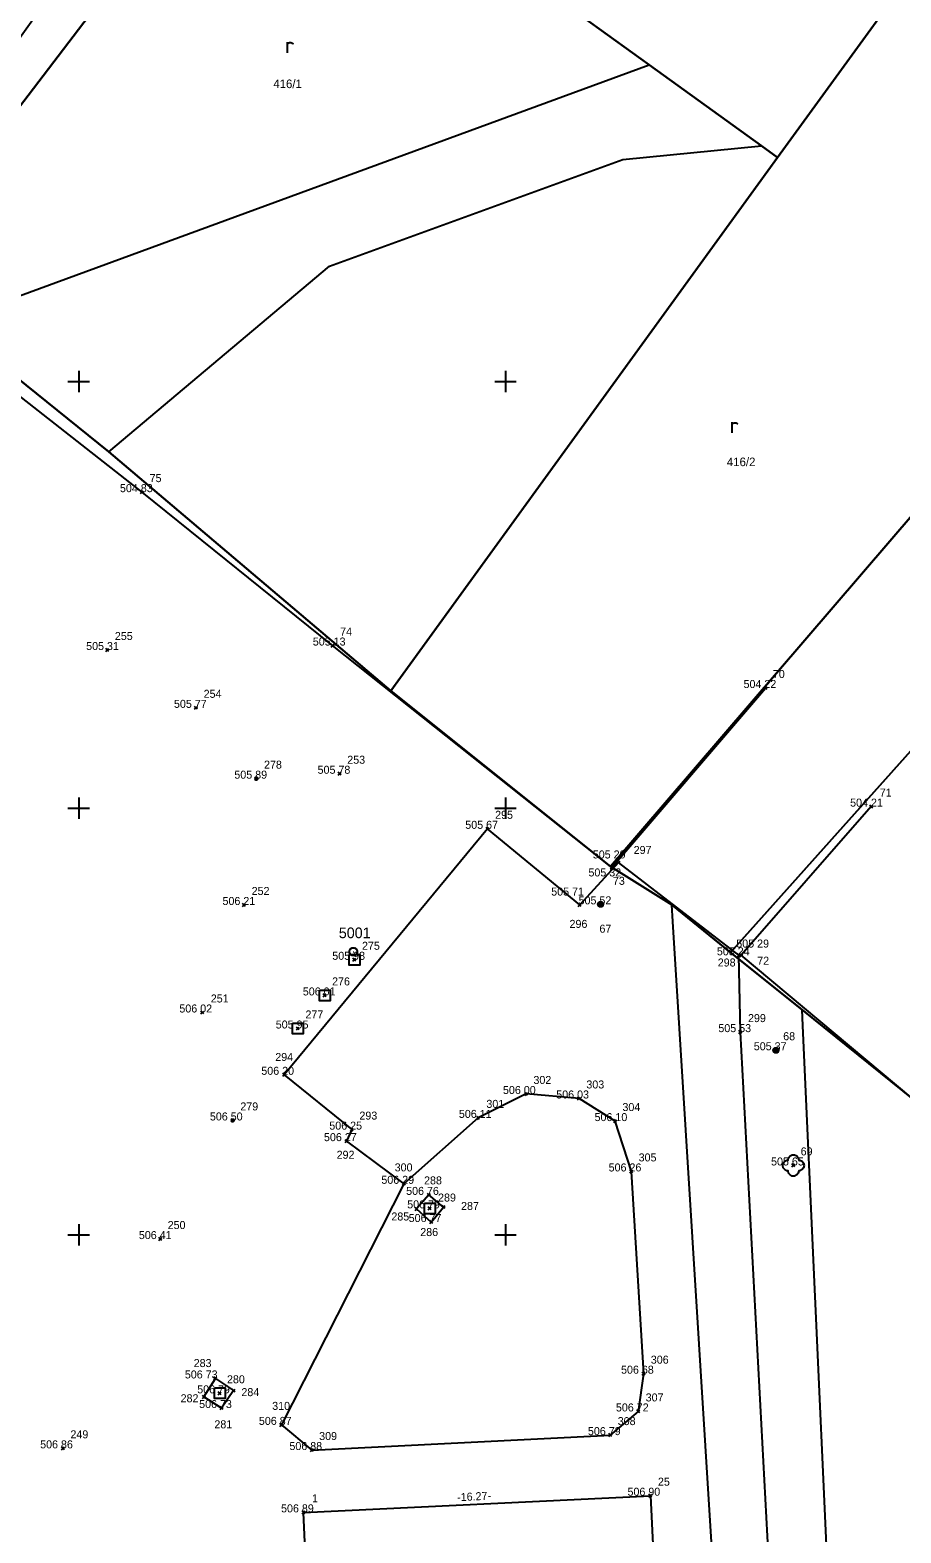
# Model space of a CAD drawing. Extents: x -408550 to -407654, y -1233019 to -1231230.
# Drawn here: x -408002.3 to -407961.5, y -1232014 to -1231943.5 of the extents above; entities that cross this region are included whole.
import ezdxf

# ---------------------------------------------------------------- set-up
doc = ezdxf.new("R2010")
doc.units = 0
for name, color, linetype in [('Level 1', 7, 'Continuous'), ('Level 11', 7, 'Continuous'), ('Level 12', 7, 'Continuous'), ('Level 14', 7, 'Continuous'), ('Level 16', 7, 'Continuous'), ('Level 20', 7, 'Continuous'), ('Level 23', 7, 'Continuous'), ('Level 26', 7, 'Continuous'), ('Level 28', 7, 'Continuous'), ('Level 30', 7, 'Continuous'), ('Level 40', 7, 'Continuous'), ('Level 41', 7, 'Continuous'), ('Level 45', 7, 'Continuous'), ('Level 47', 7, 'Continuous'), ('Level 5', 7, 'Continuous')]:
    doc.layers.add(name, color=color, linetype=linetype)

msp = doc.modelspace()

# ---------------------------------------------------------------- linework, layer by layer
at = {"layer": 'Level 1'}
for p, q in [((-408000, -1231959.5), (-408000, -1231960.5)), ((-407980, -1231959.5), (-407980, -1231960.5)), ((-408000.5, -1231960), (-407999.5, -1231960)), ((-407980.5, -1231960), (-407979.5, -1231960)), ((-408000, -1231979.5), (-408000, -1231980.5)), ((-407980, -1231979.5), (-407980, -1231980.5)), ((-408000.5, -1231980), (-407999.5, -1231980)), ((-407980.5, -1231980), (-407979.5, -1231980)), ((-408000, -1231999.5), (-408000, -1232000.5)), ((-407980, -1231999.5), (-407980, -1232000.5)), ((-408000.5, -1232000), (-407999.5, -1232000)), ((-407980.5, -1232000), (-407979.5, -1232000))]:
    msp.add_line(p, q, dxfattribs=at)
for points in [[(-407991.04, -1231886.54), (-407990.51, -1231886.91), (-407979.53, -1231894.66), (-407981.86, -1231897.95), (-407972.2, -1231905.71), (-407991.32, -1231932.1), (-408007.06, -1231952.72), (-408008.8, -1231955), (-408010, -1231954.02), (-407982.21, -1231915.1), (-407987.32, -1231909.48), (-407982.96, -1231899.31), (-407994.22, -1231890.85)], [(-407936.88, -1231940.71), (-407927.62, -1231929.33), (-407925.46, -1231926.55), (-407918.2, -1231917), (-407912.81, -1231921.49), (-407927.97, -1231939.1), (-407932.78, -1231945.57), (-407935.18, -1231948.41), (-407939.36, -1231953.09), (-407969.45, -1231986.76), (-407972.21, -1231984.54), (-407975.08, -1231982.73), (-407945.1, -1231947.81), (-407942.31, -1231945.07)], [(-407991.32, -1231932.1), (-407979.12, -1231940.92), (-407973.26, -1231945.16), (-407968, -1231948.96), (-407967.25, -1231949.5), (-407985.37, -1231974.5), (-407998.58, -1231963.3), (-408002.95, -1231959.78), (-408005.56, -1231957.64), (-408008.8, -1231955), (-408007.06, -1231952.72)], [(-407945.1, -1231947.81), (-407975.08, -1231982.73), (-407985.37, -1231974.5), (-407967.25, -1231949.5), (-407961.01, -1231940.9)], [(-407927.1, -1231965.2), (-407931.57, -1231970.36), (-407955.64, -1231997.88), (-407966.11, -1231989.44), (-407969.45, -1231986.76), (-407939.36, -1231953.09)]]:
    msp.add_lwpolyline(points, close=True, dxfattribs=at)
for points in [[(-407945.83, -1231920.05), (-407949.91, -1231925.78), (-407952.31, -1231929.14), (-407961.01, -1231940.9), (-407967.25, -1231949.5), (-407968, -1231948.96), (-407973.26, -1231945.16), (-407979.12, -1231940.92), (-407957.82, -1231911.87), (-407949.85, -1231917.72)], [(-407990.21, -1231944.59), (-407990.21, -1231944.09)], [(-407990.21, -1231944.19), (-407990.185, -1231944.157), (-407990.152, -1231944.13), (-407990.117, -1231944.117), (-407990.06, -1231944.115), (-407990.017, -1231944.122), (-407989.992, -1231944.14), (-407989.97, -1231944.165), (-407989.96, -1231944.19)], [(-408002.95, -1231959.78), (-407998.58, -1231963.3), (-407985.37, -1231974.5), (-407975.08, -1231982.73), (-407972.21, -1231984.54), (-407969.45, -1231986.76), (-407966.11, -1231989.44), (-407955.64, -1231997.88), (-407939.09, -1232011.47), (-407927.08, -1232021.88), (-407908.02, -1232037.31)], [(-407969.38, -1231962.41), (-407969.38, -1231961.91)], [(-407969.38, -1231962.01), (-407969.355, -1231961.978), (-407969.323, -1231961.95), (-407969.288, -1231961.938), (-407969.23, -1231961.935), (-407969.188, -1231961.943), (-407969.163, -1231961.96), (-407969.14, -1231961.985), (-407969.13, -1231962.01)]]:
    msp.add_lwpolyline(points, dxfattribs=at)
at = {"layer": 'Level 11'}
msp.add_lwpolyline([(-407989.46, -1232013.01), (-407973.21, -1232012.23), (-407971.98, -1232037.5), (-407977.95, -1232037.78), (-407977.733, -1232042.415), (-407976.39, -1232042.37), (-407976.14, -1232046.74), (-407977.45, -1232046.87), (-407977.009, -1232051.318), (-407974.962, -1232053.765), (-407970.82, -1232049.62), (-407949.71, -1232072.37), (-407961.89, -1232083.71), (-407983.01, -1232060.92), (-407980.3, -1232058.38), (-407984.06, -1232054.32), (-407985.01, -1232038.14), (-407988.32, -1232038.28)], close=True, dxfattribs=at)
at = {"layer": 'Level 12'}
for p, q in [((-407975.01, -1231982.78), (-407967.81, -1231974.37)), ((-407962.86, -1231979.93), (-407968.95, -1231986.9))]:
    msp.add_line(p, q, dxfattribs=at)
msp.add_lwpolyline([(-407921.23, -1232026.55), (-407939.09, -1232011.64), (-407955.83, -1231997.88), (-407968.95, -1231986.9), (-407969.06, -1231986.9), (-407974.7, -1231982.55), (-407975.01, -1231982.78), (-407988.1, -1231972.38), (-407997.03, -1231965.19), (-408008.57, -1231956.14), (-408021.93, -1231961.96), (-408037.34, -1231968.54), (-408046.88, -1231972.68)], dxfattribs=at)
at = {"layer": 'Level 14'}
msp.add_lwpolyline([(-407974.7, -1231982.55), (-407976.52, -1231984.54), (-407980.84, -1231980.97), (-407990.37, -1231992.5), (-407987.2, -1231995.07), (-407987.45, -1231995.61), (-407984.76, -1231997.61)], dxfattribs=at)
msp.add_lwpolyline([(-407984.76, -1231997.61), (-407990.5, -1232008.91), (-407989.07, -1232010.09), (-407975.08, -1232009.39), (-407973.77, -1232008.28), (-407973.52, -1232006.51), (-407974.1, -1231997.03), (-407974.86, -1231994.67), (-407976.55, -1231993.61), (-407979.03, -1231993.4), (-407981.28, -1231994.52)], close=True, dxfattribs=at)
at = {"layer": 'Level 16'}
msp.add_lwpolyline([(-407975.55, -1232046.38), (-407966.48, -1232045.77), (-407966.78, -1232037.84), (-407966.87, -1232034.48), (-407966.71, -1232034.46), (-407967.34, -1232021.13), (-407968.99, -1231990.5), (-407969.06, -1231986.9)], dxfattribs=at)
for points in [[(-407983.59, -1231998.13), (-407984.17, -1231998.79), (-407983.48, -1231999.4), (-407982.9, -1231998.7)], [(-407994.13, -1232007.6), (-407993.59, -1232006.73), (-407992.74, -1232007.3), (-407993.3, -1232008.12)]]:
    msp.add_lwpolyline(points, close=True, dxfattribs=at)
at = {"layer": 'Level 20'}
for points in [[(-407987.33, -1231986.86), (-407986.83, -1231986.86), (-407986.83, -1231987.36), (-407987.33, -1231987.36)], [(-407988.72, -1231988.53), (-407988.22, -1231988.53), (-407988.22, -1231989.03), (-407988.72, -1231989.03)], [(-407989.98, -1231990.08), (-407989.48, -1231990.08), (-407989.48, -1231990.58), (-407989.98, -1231990.58)], [(-407983.8, -1231998.51), (-407983.3, -1231998.51), (-407983.3, -1231999.01), (-407983.8, -1231999.01)], [(-407993.64, -1232007.18), (-407993.14, -1232007.18), (-407993.14, -1232007.68), (-407993.64, -1232007.68)]]:
    msp.add_lwpolyline(points, close=True, dxfattribs=at)
at = {"layer": 'Level 23'}
for points in [[(-407996.961, -1231965.259), (-407997.099, -1231965.121)], [(-407997.099, -1231965.259), (-407996.961, -1231965.121)], [(-407998.591, -1231972.659), (-407998.729, -1231972.521)], [(-407998.729, -1231972.659), (-407998.591, -1231972.521)], [(-407988.031, -1231972.449), (-407988.169, -1231972.311)], [(-407988.169, -1231972.449), (-407988.031, -1231972.311)], [(-407967.741, -1231974.439), (-407967.879, -1231974.301)], [(-407967.879, -1231974.439), (-407967.741, -1231974.301)], [(-407994.431, -1231975.369), (-407994.569, -1231975.231)], [(-407994.569, -1231975.369), (-407994.431, -1231975.231)], [(-407991.601, -1231978.689), (-407991.739, -1231978.551)], [(-407991.739, -1231978.689), (-407991.601, -1231978.551)], [(-407987.701, -1231978.459), (-407987.839, -1231978.321)], [(-407987.839, -1231978.459), (-407987.701, -1231978.321)], [(-407962.791, -1231979.999), (-407962.929, -1231979.861)], [(-407962.929, -1231979.999), (-407962.791, -1231979.861)], [(-407980.771, -1231981.039), (-407980.909, -1231980.901)], [(-407980.909, -1231981.039), (-407980.771, -1231980.901)], [(-407974.941, -1231982.849), (-407975.079, -1231982.711)], [(-407975.079, -1231982.849), (-407974.941, -1231982.711)], [(-407974.631, -1231982.619), (-407974.769, -1231982.481)], [(-407974.769, -1231982.619), (-407974.631, -1231982.481)], [(-407992.181, -1231984.609), (-407992.319, -1231984.471)], [(-407992.319, -1231984.609), (-407992.181, -1231984.471)], [(-407976.451, -1231984.609), (-407976.589, -1231984.471)], [(-407976.589, -1231984.609), (-407976.451, -1231984.471)], [(-407975.471, -1231984.579), (-407975.609, -1231984.441)], [(-407975.609, -1231984.579), (-407975.471, -1231984.441)], [(-407968.991, -1231986.969), (-407969.129, -1231986.831)], [(-407969.129, -1231986.969), (-407968.991, -1231986.831)], [(-407968.881, -1231986.969), (-407969.019, -1231986.831)], [(-407969.019, -1231986.969), (-407968.881, -1231986.831)], [(-407987.011, -1231987.179), (-407987.149, -1231987.041)], [(-407987.149, -1231987.179), (-407987.011, -1231987.041)], [(-407988.401, -1231988.849), (-407988.539, -1231988.711)], [(-407988.539, -1231988.849), (-407988.401, -1231988.711)], [(-407994.141, -1231989.649), (-407994.279, -1231989.511)], [(-407994.279, -1231989.649), (-407994.141, -1231989.511)], [(-407989.661, -1231990.399), (-407989.799, -1231990.261)], [(-407989.799, -1231990.399), (-407989.661, -1231990.261)], [(-407968.921, -1231990.569), (-407969.059, -1231990.431)], [(-407969.059, -1231990.569), (-407968.921, -1231990.431)], [(-407967.261, -1231991.419), (-407967.399, -1231991.281)], [(-407967.399, -1231991.419), (-407967.261, -1231991.281)], [(-407990.301, -1231992.569), (-407990.439, -1231992.431)], [(-407990.439, -1231992.569), (-407990.301, -1231992.431)], [(-407978.961, -1231993.469), (-407979.099, -1231993.331)], [(-407979.099, -1231993.469), (-407978.961, -1231993.331)], [(-407976.481, -1231993.679), (-407976.619, -1231993.541)], [(-407976.619, -1231993.679), (-407976.481, -1231993.541)], [(-407992.711, -1231994.709), (-407992.849, -1231994.571)], [(-407992.849, -1231994.709), (-407992.711, -1231994.571)], [(-407981.211, -1231994.589), (-407981.349, -1231994.451)], [(-407981.349, -1231994.589), (-407981.211, -1231994.451)], [(-407974.791, -1231994.739), (-407974.929, -1231994.601)], [(-407974.929, -1231994.739), (-407974.791, -1231994.601)], [(-407987.131, -1231995.139), (-407987.269, -1231995.001)], [(-407987.269, -1231995.139), (-407987.131, -1231995.001)], [(-407987.381, -1231995.679), (-407987.519, -1231995.541)], [(-407987.519, -1231995.679), (-407987.381, -1231995.541)], [(-407966.441, -1231996.819), (-407966.579, -1231996.681)], [(-407966.579, -1231996.819), (-407966.441, -1231996.681)], [(-407984.691, -1231997.679), (-407984.829, -1231997.541)], [(-407984.829, -1231997.679), (-407984.691, -1231997.541)], [(-407974.031, -1231997.099), (-407974.169, -1231996.961)], [(-407974.169, -1231997.099), (-407974.031, -1231996.961)], [(-407983.521, -1231998.199), (-407983.659, -1231998.061)], [(-407983.659, -1231998.199), (-407983.521, -1231998.061)], [(-407984.101, -1231998.859), (-407984.239, -1231998.721)], [(-407984.239, -1231998.859), (-407984.101, -1231998.721)], [(-407983.481, -1231998.829), (-407983.619, -1231998.691)], [(-407983.619, -1231998.829), (-407983.481, -1231998.691)], [(-407982.831, -1231998.769), (-407982.969, -1231998.631)], [(-407982.969, -1231998.769), (-407982.831, -1231998.631)], [(-407983.411, -1231999.469), (-407983.549, -1231999.331)], [(-407983.549, -1231999.469), (-407983.411, -1231999.331)], [(-407996.101, -1232000.269), (-407996.239, -1232000.131)], [(-407996.239, -1232000.269), (-407996.101, -1232000.131)], [(-407993.521, -1232006.799), (-407993.659, -1232006.661)], [(-407993.659, -1232006.799), (-407993.521, -1232006.661)], [(-407973.451, -1232006.579), (-407973.589, -1232006.441)], [(-407973.589, -1232006.579), (-407973.451, -1232006.441)], [(-407993.321, -1232007.499), (-407993.459, -1232007.361)], [(-407993.459, -1232007.499), (-407993.321, -1232007.361)], [(-407992.671, -1232007.369), (-407992.809, -1232007.231)], [(-407992.809, -1232007.369), (-407992.671, -1232007.231)], [(-407994.061, -1232007.669), (-407994.199, -1232007.531)], [(-407994.199, -1232007.669), (-407994.061, -1232007.531)], [(-407993.231, -1232008.189), (-407993.369, -1232008.051)], [(-407993.369, -1232008.189), (-407993.231, -1232008.051)], [(-407990.431, -1232008.979), (-407990.569, -1232008.841)], [(-407990.569, -1232008.979), (-407990.431, -1232008.841)], [(-407973.701, -1232008.349), (-407973.839, -1232008.211)], [(-407973.839, -1232008.349), (-407973.701, -1232008.211)], [(-407975.011, -1232009.459), (-407975.149, -1232009.321)], [(-407975.149, -1232009.459), (-407975.011, -1232009.321)], [(-408000.671, -1232010.079), (-408000.809, -1232009.941)], [(-408000.809, -1232010.079), (-408000.671, -1232009.941)], [(-407989.001, -1232010.159), (-407989.139, -1232010.021)], [(-407989.139, -1232010.159), (-407989.001, -1232010.021)], [(-407973.141, -1232012.299), (-407973.279, -1232012.161)], [(-407973.279, -1232012.299), (-407973.141, -1232012.161)], [(-407989.391, -1232013.079), (-407989.529, -1232012.941)], [(-407989.529, -1232013.079), (-407989.391, -1232012.941)]]:
    msp.add_lwpolyline(points, dxfattribs=at)
at = {"layer": 'Level 28'}
msp.add_lwpolyline([(-407966.01, -1231996.75), (-407966.035, -1231996.858), (-407966.104, -1231996.946), (-407966.204, -1231996.994), (-407966.26, -1231997), (-407966.285, -1231997.108), (-407966.354, -1231997.196), (-407966.454, -1231997.244), (-407966.566, -1231997.244), (-407966.666, -1231997.196), (-407966.735, -1231997.108), (-407966.76, -1231997), (-407966.816, -1231996.994), (-407966.916, -1231996.946), (-407966.985, -1231996.858), (-407967.01, -1231996.75), (-407966.985, -1231996.642), (-407966.916, -1231996.554), (-407966.816, -1231996.506), (-407966.76, -1231996.5), (-407966.735, -1231996.392), (-407966.666, -1231996.304), (-407966.566, -1231996.256), (-407966.454, -1231996.256), (-407966.354, -1231996.304), (-407966.285, -1231996.392), (-407966.26, -1231996.5), (-407966.204, -1231996.506), (-407966.104, -1231996.554), (-407966.035, -1231996.642)], close=True, dxfattribs=at)
msp.add_lwpolyline([(-407966.522, -1231996.75), (-407966.51, -1231996.75), (-407966.498, -1231996.75)], dxfattribs=at)
at = {"layer": 'Level 30'}
msp.add_lwpolyline([(-407987.082, -1231986.549), (-407986.998, -1231986.598), (-407986.949, -1231986.682), (-407986.949, -1231986.778), (-407986.998, -1231986.862), (-407987.082, -1231986.911), (-407987.178, -1231986.911), (-407987.262, -1231986.862), (-407987.311, -1231986.778), (-407987.311, -1231986.682), (-407987.262, -1231986.598), (-407987.178, -1231986.549)], close=True, dxfattribs=at)
msp.add_lwpolyline([(-407987.142, -1231986.73), (-407987.118, -1231986.73)], dxfattribs=at)
at = {"layer": 'Level 45'}
for points in [[(-407975.579, -1231984.391), (-407975.501, -1231984.391), (-407975.439, -1231984.436), (-407975.415, -1231984.51), (-407975.439, -1231984.584), (-407975.501, -1231984.629), (-407975.579, -1231984.629), (-407975.641, -1231984.584), (-407975.665, -1231984.51), (-407975.641, -1231984.436), (-407975.579, -1231984.391), (-407975.57, -1231984.4), (-407975.51, -1231984.4), (-407975.47, -1231984.42), (-407975.61, -1231984.42), (-407975.63, -1231984.44), (-407975.45, -1231984.44), (-407975.45, -1231984.46), (-407975.63, -1231984.46), (-407975.64, -1231984.48), (-407975.44, -1231984.48), (-407975.43, -1231984.5), (-407975.65, -1231984.5), (-407975.65, -1231984.52), (-407975.43, -1231984.52), (-407975.438, -1231984.54), (-407975.641, -1231984.54), (-407975.64, -1231984.56), (-407975.438, -1231984.56), (-407975.45, -1231984.58), (-407975.63, -1231984.58), (-407975.61, -1231984.6), (-407975.47, -1231984.6), (-407975.497, -1231984.62), (-407975.582, -1231984.62)], [(-407967.369, -1231991.231), (-407967.291, -1231991.231), (-407967.229, -1231991.277), (-407967.205, -1231991.35), (-407967.229, -1231991.424), (-407967.291, -1231991.469), (-407967.369, -1231991.469), (-407967.431, -1231991.424), (-407967.455, -1231991.35), (-407967.431, -1231991.277), (-407967.369, -1231991.231), (-407967.36, -1231991.24), (-407967.3, -1231991.24), (-407967.26, -1231991.26), (-407967.4, -1231991.26), (-407967.42, -1231991.28), (-407967.24, -1231991.28), (-407967.24, -1231991.3), (-407967.42, -1231991.3), (-407967.43, -1231991.32), (-407967.23, -1231991.32), (-407967.22, -1231991.34), (-407967.44, -1231991.34), (-407967.44, -1231991.36), (-407967.22, -1231991.36), (-407967.228, -1231991.38), (-407967.431, -1231991.38), (-407967.43, -1231991.4), (-407967.228, -1231991.4), (-407967.24, -1231991.42), (-407967.42, -1231991.42), (-407967.4, -1231991.44), (-407967.26, -1231991.44), (-407967.287, -1231991.46), (-407967.372, -1231991.46)]]:
    msp.add_lwpolyline(points, dxfattribs=at)
at = {"layer": 'Level 47'}
for points in [[(-407991.639, -1231978.566), (-407991.608, -1231978.62), (-407991.639, -1231978.674), (-407991.701, -1231978.674), (-407991.732, -1231978.62), (-407991.701, -1231978.566), (-407991.639, -1231978.566), (-407991.64, -1231978.57), (-407991.7, -1231978.57), (-407991.7, -1231978.59), (-407991.64, -1231978.59), (-407991.62, -1231978.61), (-407991.72, -1231978.61), (-407991.72, -1231978.63), (-407991.62, -1231978.63), (-407991.64, -1231978.65), (-407991.7, -1231978.65), (-407991.693, -1231978.67), (-407991.646, -1231978.67)], [(-407992.749, -1231994.586), (-407992.718, -1231994.64), (-407992.749, -1231994.694), (-407992.811, -1231994.694), (-407992.842, -1231994.64), (-407992.811, -1231994.586), (-407992.749, -1231994.586), (-407992.75, -1231994.59), (-407992.81, -1231994.59), (-407992.81, -1231994.61), (-407992.75, -1231994.61), (-407992.73, -1231994.63), (-407992.83, -1231994.63), (-407992.83, -1231994.65), (-407992.73, -1231994.65), (-407992.75, -1231994.67), (-407992.81, -1231994.67), (-407992.803, -1231994.69), (-407992.756, -1231994.69)]]:
    msp.add_lwpolyline(points, dxfattribs=at)
at = {"layer": 'Level 5'}
for p, q in [((-408002.77, -1231955.98), (-407973.26, -1231945.16)), ((-407974.5, -1231949.59), (-407968, -1231948.96)), ((-407988.25, -1231954.59), (-407974.5, -1231949.59)), ((-407998.58, -1231963.3), (-407988.25, -1231954.59)), ((-407966.11, -1231989.44), (-407966.08, -1231990.2)), ((-407966.08, -1231990.2), (-407963.9, -1232038.18))]:
    msp.add_line(p, q, dxfattribs=at)
msp.add_lwpolyline([(-407968.26, -1232014.87), (-407970.32, -1232014.9), (-407972.16, -1231985.32), (-407972.21, -1231984.54)], dxfattribs=at)

# ---------------------------------------------------------------- texts
at = {"layer": 'Level 1'}
for s, p in [('416/1', (-407990.879, -1231946.25)), ('416/2', (-407969.626, -1231963.97))]:
    msp.add_text(s, height=0.4, dxfattribs=at).set_placement(p)
msp.add_text('-16.27-', height=0.375, rotation=2.7502, dxfattribs=at).set_placement((-407982.256, -1232012.489))
at = {"layer": 'Level 26'}
for s, p in [('75', (-407996.676, -1231964.72)), ('255', (-407998.304, -1231972.12)), ('74', (-407987.746, -1231971.91)), ('70', (-407967.472, -1231973.9)), ('254', (-407994.144, -1231974.83)), ('278', (-407991.314, -1231978.15)), ('253', (-407987.414, -1231977.92)), ('71', (-407962.461, -1231979.46)), ('295', (-407980.485, -1231980.5)), ('297', (-407973.993, -1231982.149)), ('73', (-407974.965, -1231983.596)), ('252', (-407991.894, -1231984.07)), ('296', (-407976.998, -1231985.614)), ('67', (-407975.596, -1231985.839)), ('275', (-407986.724, -1231986.64)), ('72', (-407968.202, -1231987.34)), ('298', (-407970.053, -1231987.423)), ('276', (-407988.124, -1231988.31)), ('251', (-407993.809, -1231989.11)), ('277', (-407989.374, -1231989.86)), ('299', (-407968.636, -1231990.03)), ('68', (-407966.986, -1231990.88)), ('294', (-407990.788, -1231991.853)), ('302', (-407978.69, -1231992.93)), ('303', (-407976.21, -1231993.14)), ('279', (-407992.425, -1231994.17)), ('301', (-407980.895, -1231994.05)), ('304', (-407974.52, -1231994.2)), ('293', (-407986.845, -1231994.6)), ('292', (-407987.912, -1231996.435)), ('305', (-407973.76, -1231996.56)), ('69', (-407966.168, -1231996.28)), ('300', (-407985.192, -1231997.028)), ('288', (-407983.815, -1231997.638)), ('289', (-407983.159, -1231998.441)), ('285', (-407985.347, -1231999.329)), ('287', (-407982.081, -1231998.836)), ('250', (-407995.83, -1231999.73)), ('286', (-407983.993, -1232000.059)), ('283', (-407994.611, -1232006.2)), ('306', (-407973.19, -1232006.04)), ('280', (-407993.05, -1232006.96)), ('284', (-407992.375, -1232007.563)), ('307', (-407973.43, -1232007.81)), ('282', (-407995.223, -1232007.849)), ('310', (-407990.931, -1232008.206)), ('281', (-407993.64, -1232009.069)), ('308', (-407974.74, -1232008.92)), ('249', (-408000.385, -1232009.54)), ('309', (-407988.731, -1232009.62)), ('25', (-407972.856, -1232011.76)), ('1', (-407989.064, -1232012.54))]:
    msp.add_text(s, height=0.375, dxfattribs=at).set_placement(p)
at = {"layer": 'Level 40'}
for s, p in [('504 83', (-407998.064, -1231965.19)), ('505 31', (-407999.65, -1231972.59)), ('505 13', (-407989.028, -1231972.38)), ('504 22', (-407968.844, -1231974.37)), ('505 77', (-407995.534, -1231975.3)), ('505 89', (-407992.705, -1231978.62)), ('505 78', (-407988.804, -1231978.39)), ('504 21', (-407963.85, -1231979.93)), ('505 67', (-407981.884, -1231980.97)), ('505 20', (-407975.908, -1231982.359)), ('505 32', (-407976.112, -1231983.202)), ('506 21', (-407993.26, -1231984.54)), ('505 71', (-407977.857, -1231984.099)), ('505 52', (-407976.574, -1231984.51)), ('505 29', (-407969.184, -1231986.536)), ('505 98', (-407988.115, -1231987.11)), ('505 24', (-407970.094, -1231986.9)), ('506 01', (-407989.497, -1231988.78)), ('506 02', (-407995.281, -1231989.58)), ('505 95', (-407990.765, -1231990.33)), ('505 53', (-407970.024, -1231990.5)), ('505 37', (-407968.364, -1231991.35)), ('506 20', (-407991.441, -1231992.5)), ('506 00', (-407980.117, -1231993.4)), ('506 03', (-407977.621, -1231993.61)), ('506 50', (-407993.851, -1231994.64)), ('506 25', (-407988.255, -1231995.07)), ('506 11', (-407982.184, -1231994.52)), ('506 10', (-407975.825, -1231994.67)), ('506 27', (-407988.505, -1231995.61)), ('506 26', (-407975.165, -1231997.03)), ('505 65', (-407967.554, -1231996.75)), ('506 29', (-407985.816, -1231997.61)), ('506 76', (-407984.655, -1231998.13)), ('506 79', (-407984.606, -1231998.76)), ('506 77', (-407984.535, -1231999.4)), ('506 41', (-407997.18, -1232000.2)), ('506 73', (-407995.025, -1232006.733)), ('506 68', (-407974.585, -1232006.51)), ('506 79', (-407994.446, -1232007.43)), ('506 73', (-407994.355, -1232008.12)), ('506 72', (-407974.825, -1232008.28)), ('506 87', (-407991.555, -1232008.91)), ('506 79', (-407976.136, -1232009.39)), ('506 86', (-408001.805, -1232010.01)), ('506 88', (-407990.125, -1232010.09)), ('506 90', (-407974.282, -1232012.23)), ('506 89', (-407990.516, -1232013.01))]:
    msp.add_text(s, height=0.375, dxfattribs=at).set_placement(p)
at = {"layer": 'Level 41'}
msp.add_text('5001', height=0.5, dxfattribs=at).set_placement((-407987.808, -1231986.096))

doc.saveas('drawing.dxf')
